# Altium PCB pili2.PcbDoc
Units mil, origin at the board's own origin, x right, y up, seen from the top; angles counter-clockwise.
Board outline 3240 x 2595 mil, 2 copper layers (Top Layer, Bottom Layer); 29 components, 28 nets, 78 pads, 0 vias.
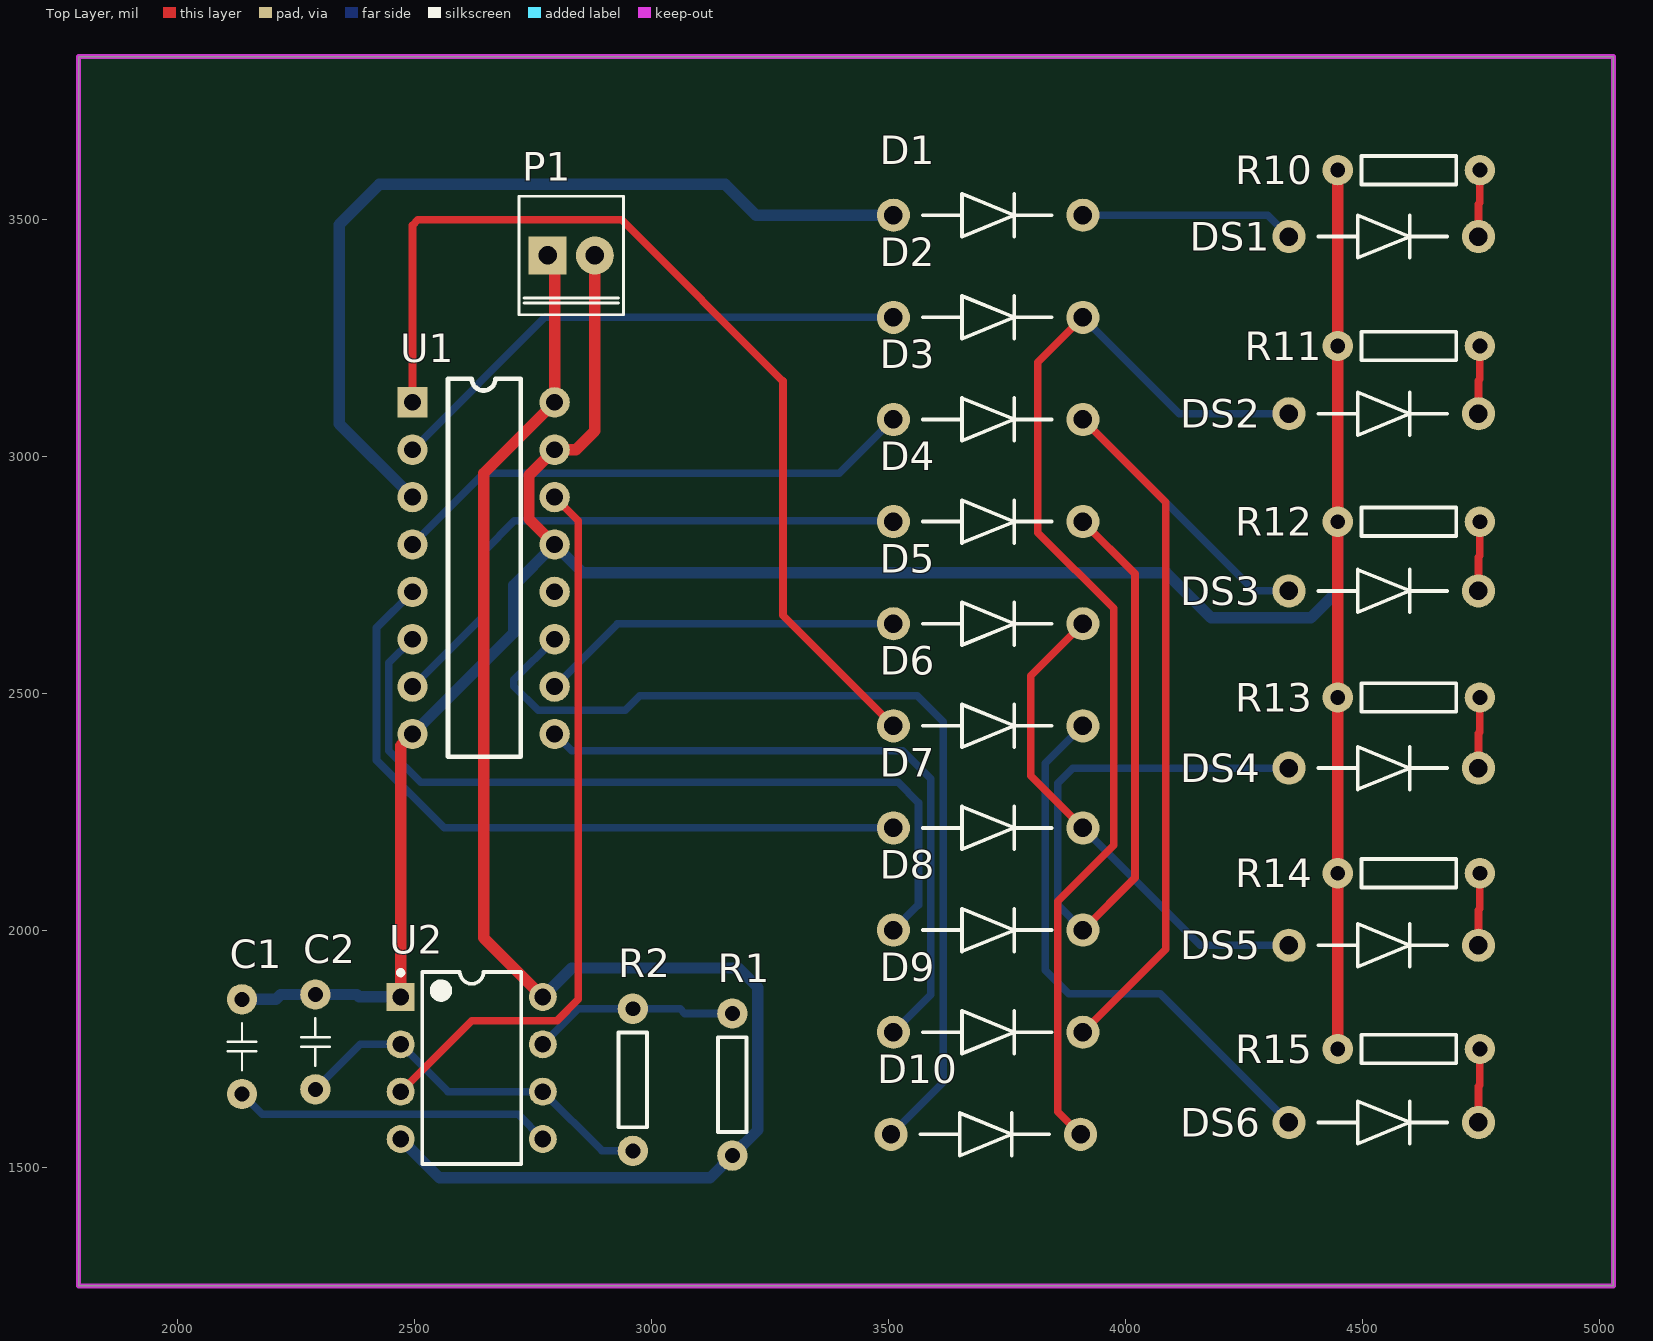
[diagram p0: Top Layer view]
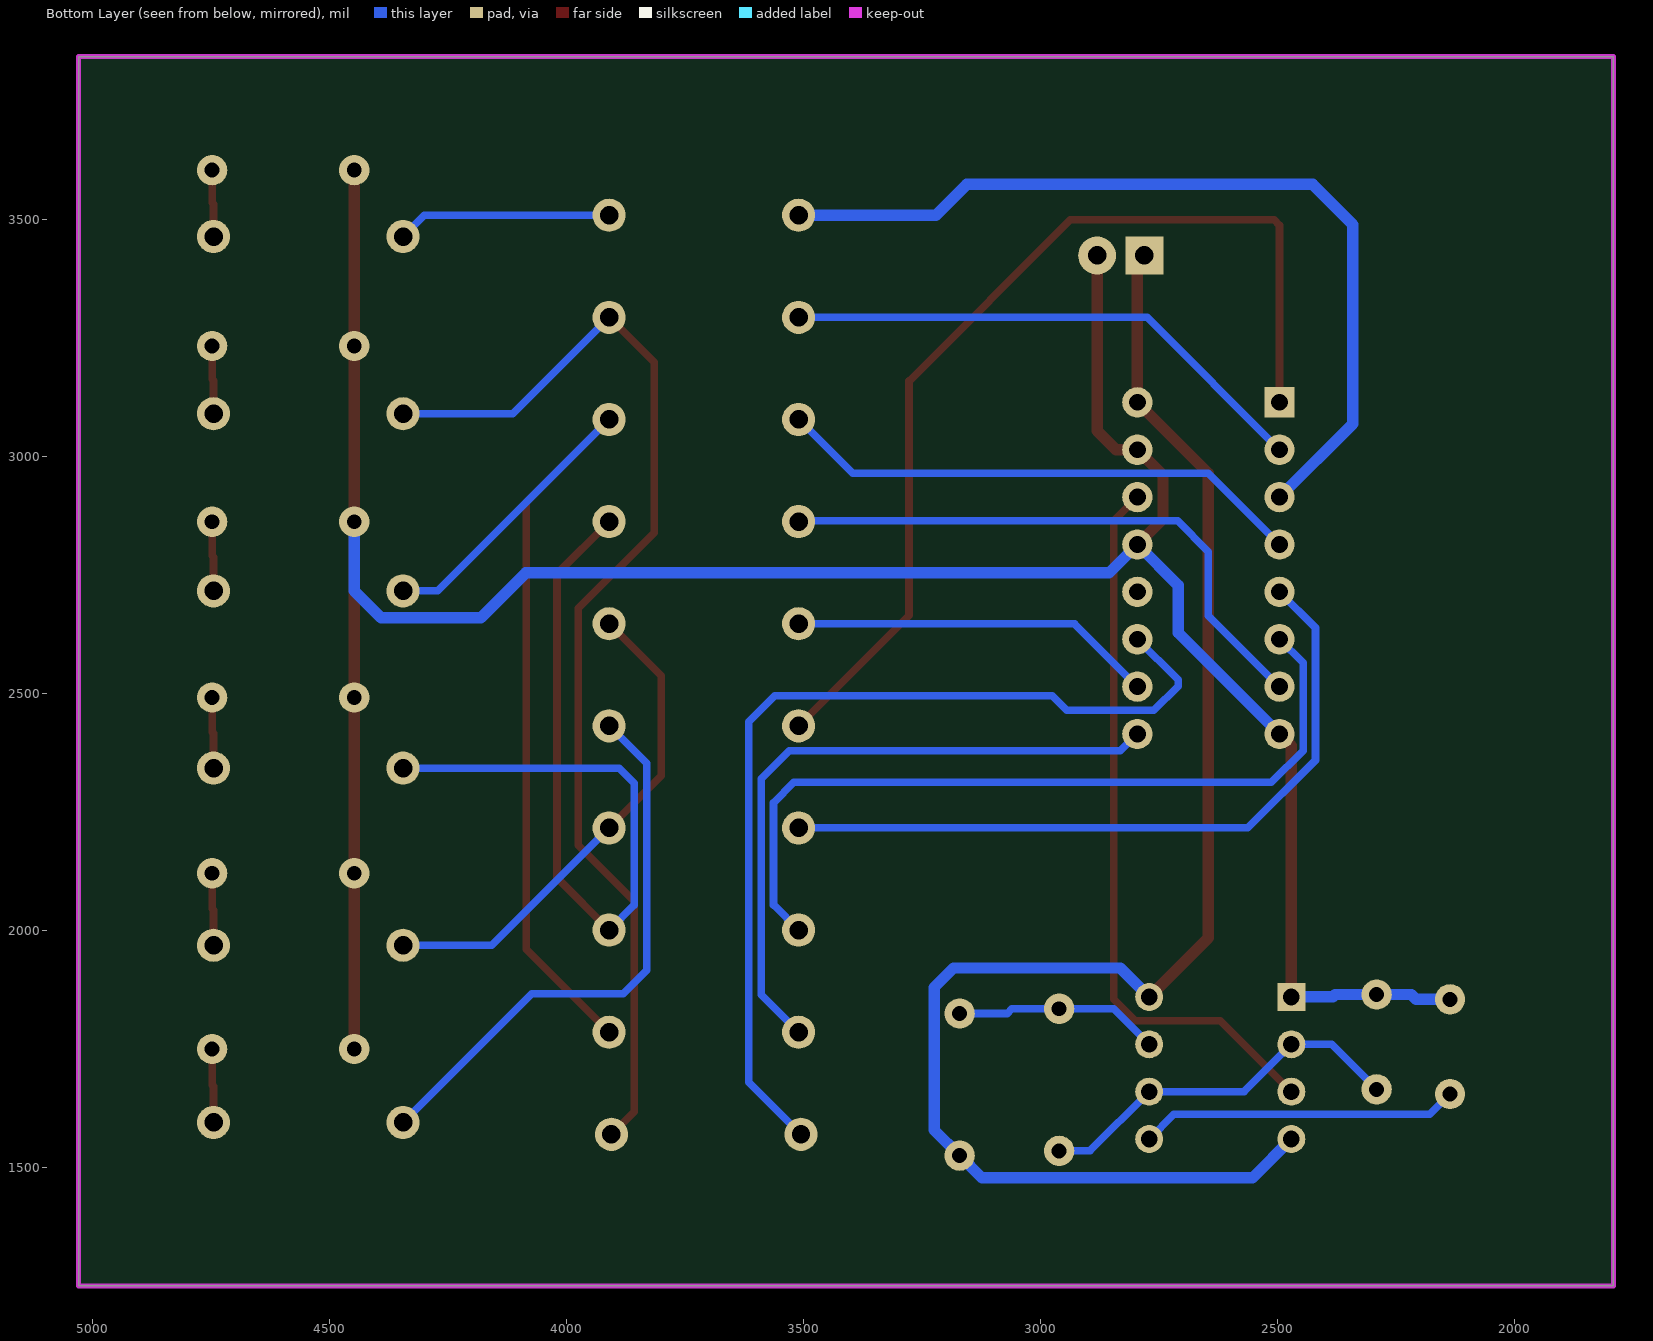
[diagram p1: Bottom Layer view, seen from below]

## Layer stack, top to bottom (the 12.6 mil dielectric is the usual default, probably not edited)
Top Layer: signal copper 1.4
Dielectric: dielectric 12.6, FR-4, Dk 4.8
Bottom Layer: signal copper 1.4

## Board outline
1790,1250 1790,3845 5030,3845 5030,1250

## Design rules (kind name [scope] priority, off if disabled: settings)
Clearance [All] p1: gap=10
PolygonConnect [All] p1: connectstyle=Relief reliefconductorwidth=10 reliefentries=4 polygonreliefangle="90 Angle" airgapwidth=10
RoutingVias [All] p1: holewidth=28 width=50 viastyle="Through Hole" minholewidth=28 minwidth=50 maxholewidth=28 maxwidth=50
SolderMaskExpansion [All] p1: expansion=4
Width Width_power [InNetClass('power')] p1: maxlimit=40 minlimit=10 preferedwidth=24
Width [All] p2: maxlimit=40 minlimit=10 preferedwidth=16
28 further rules are at their usual default settings.

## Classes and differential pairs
net class power: GND VCC

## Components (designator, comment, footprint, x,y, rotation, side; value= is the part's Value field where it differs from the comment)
C1 "Cap" "C200 - 1" 2135,1755 r180 top
C2 "Cap" "C200 - 1" 2290,1765 r180 top
D1 "1N914" D400 3710,3510 r0 top
D2 "1N914" D400 3710,3294.44 r0 top
D3 "1N914" D400 3710,3078.89 r0 top
D4 "1N914" D400 3710,2863.33 r0 top
D5 "1N914" D400 3710,2647.78 r0 top
D6 "1N914" D400 3710,2432.22 r0 top
D7 "1N914" D400 3710,2216.67 r0 top
D8 "1N914" D400 3710,2001.11 r0 top
D9 "1N914" D400 3710,1785.56 r0 top
D10 "1N914" D400 3705,1570 r0 top
DS1 "1N914" D400-1 4545,3465 r0 top
DS2 "1N914" D400-1 4545,3091 r0 top
DS3 "1N914" D400-1 4545,2717 r0 top
DS4 "1N914" D400-1 4545,2343 r0 top
DS5 "1N914" D400-1 4545,1969 r0 top
DS6 "1N914" D400-1 4545,1595 r0 top
P1 "+5V" "HEADER 2 PW-0.2" 2830,3425 r270 top
R1 "1k" AXIAL-0.3 3170,1675 r270 top
R2 "1k" AXIAL-0.3 2960,1685 r90 top
R10 "1k" AXIAL-0.3 4598,3605 r0 top
R11 "1k" AXIAL-0.3 4598,3234 r0 top
R12 "1k" AXIAL-0.3 4598,2863 r0 top
R13 "1k" AXIAL-0.3 4598,2492 r0 top
R14 "1k" AXIAL-0.3 4598,2121 r0 top
R15 "1k" AXIAL-0.3 4598,1750 r0 top
U1 "CD4017BCN" DIP16_4017 2495,3115 r270 top
U2 "LMC555CN" N08E_555 2620,1710 r0 top

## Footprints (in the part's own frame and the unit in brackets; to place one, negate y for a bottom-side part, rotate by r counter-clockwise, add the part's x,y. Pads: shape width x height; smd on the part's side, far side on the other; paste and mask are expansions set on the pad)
AXIAL-0.3 [mil] "0.3\" Resistor; 2 Leads"
  round 64 hole 31.5: 1(-150,0) 2(150,0)
  silkscreen extent -100,-30 100,30, body extent -161,-41 165,41, height 88
"C200 - 1" [mil] "吵病筿甧竟"
  round 64 hole 31.5: 1(0,100) 2(0,-100)
  silkscreen extent -30,-50 30,50, body extent -19,-132 21,143, height 282
D400 [mil]
  round 70 hole 39: 1(-200,0) 2(200,0)
  silkscreen extent -138,-45 134,45, body extent -216,-79 217,78, height 161
D400-1 [mil]
  round 70 hole 39: 1(-200,0) 2(200,0)
  silkscreen extent -138,-45 134,45, body extent -216,-59 217,59, height 141
DIP16_4017 [mil] "4017"
  rect 64x64 hole 35.43: 1(0,0)
  round 64 hole 35.43: 2(100,0) 3(200,0) 4(300,0) 5(400,0) 6(500,0) 7(600,0) 8(700,0) 9(700,300) 10(600,300) 11(500,300) 12(400,300) 13(300,300) 14(200,300) 15(100,300) 16(0,300)
  silkscreen extent -50,75 748,228, body extent -50,-4 748,304, height 177
"HEADER 2 PW-0.2" [mil]
  rect 80x80 hole 39: 1(0,-50)
  round 80 hole 39: 2(0,50)
  silkscreen extent -125,-110 125,110, body extent -124,-110 125,113, height 433
N08E_555 [mm]
  rect 1.5x1.5 hole 0.9: 1(-3.81,3.81)
  round 1.5 hole 0.9: 2(-3.81,1.27) 3(-3.81,-1.27) 4(-3.81,-3.81) 5(3.81,-3.81) 6(3.81,-1.27) 7(3.81,1.27) 8(3.81,3.81)
  silkscreen extent -3.93,-5.15 2.65,5.23, body extent -3.92,-5.15 3.92,5.15, height 4.5

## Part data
C1 C2: "Capacitor"
D1 D2 D3 D4 D5 D6 D7 D8 D9 D10 DS1 DS2 DS3 DS4 DS5 DS6: "High Conductance Fast Diode"
P1: library part "Header 2", "Header, 2-Pin"
R1 R2 R10 R11 R12 R13 R14 R15: library part Res, "Resistor"
U1: "Decade Counter/Divider with 10 Decoded Outputs"
U2: "CMOS Timer"

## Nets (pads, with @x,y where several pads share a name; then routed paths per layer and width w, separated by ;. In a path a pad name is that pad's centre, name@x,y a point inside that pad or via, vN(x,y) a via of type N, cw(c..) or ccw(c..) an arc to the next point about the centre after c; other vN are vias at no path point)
GND: C1.2 C2.2 P1.2 R10.1 R11.1 R12.1 R13.1 R14.1 R15.1 U1.8 U1.13 U1.15 U2.1 | length 5888.9
  Top Layer w24: U2.1 2470,2390 U1.8 ; U1.13 2741,2869 2741,2961 U1.15 2840,3015 2880,3055 P1.2 ; R15.1 R14.1 R13.1 R12.1 R11.1 R10.1
  Bottom Layer w24: C1.2 2207,1855 2217,1865 C2.2 2377,1865 2382,1860 U2.1 ; U1.8 2709,2629 2709,2729 U1.13 2855,2755 4086,2755 4181,2660 4391,2660 4448,2717 R12.1
NetC1_1: C1.1 U2.5 | length 674.4
  Bottom Layer w16: C1.1 2178,1612 2718,1612 U2.5
NetD1_1: D1.1 U1.3 | length 1871.3
  Bottom Layer w24: U1.3 2340,3070 2340,3490 2425,3575 3155,3575 3220,3510 D1.1
NetD2_1: D2.1 U1.2 | length 1130.7
  Bottom Layer w16: U1.2 2774.44,3294.44 D2.1
NetD3_1: D3.1 U1.4 | length 1124.3
  Bottom Layer w16: U1.4 2645,2965 3396.11,2965 D3.1
NetD4_1: D4.1 U1.7 | length 1240.7
  Bottom Layer w16: U1.7 2645,2665 2645,2800 2710,2865 3485,2865 3485,2863.33 D4.1
NetD5_1: D5.1 U1.10 | length 770
  Bottom Layer w16: U1.10 2927.78,2647.78 D5.1
NetD6_1: D6.1 U1.1 | length 2125.7
  Top Layer w16: U1.1 2495,3489 2506,3500 2937,3500 3277,3160 3277,2665.22 D6.1
NetD7_1: D7.1 U1.5 | length 1536.9
  Bottom Layer w16: U1.5 2419,2639 2419,2360 2562.33,2216.67 D7.1
NetD8_1: D8.1 U1.6 | length 1710.1
  Bottom Layer w16: U1.6 2445,2565 2445,2380 2512.23,2312.77 3520.23,2312.77 3563,2270 3563,2054.11 D8.1
NetD9_1: D9.1 U1.9 | length 1400.5
  Bottom Layer w16: U1.9 2830.78,2379.22 3529.78,2379.22 3589,2320 3589,1864.56 D9.1
NetD10_1: D10.1 U1.11 | length 2013.9
  Bottom Layer w16: U1.11 2709,2529 2709,2516 2760,2465 2944,2465 2975,2496 3560,2496 3615,2441 3615,1680 D10.1
NetDS1_2: DS1.2 R10.2 | length 141.2
  Top Layer w16: DS1.2 4745,3533 4748,3536 R10.2
NetDS2_2: DS2.2 R11.2 | length 144.2
  Top Layer w16: DS2.2 4745,3161 4748,3164 R11.2
NetDS3_2: DS3.2 R12.2 | length 147.2
  Top Layer w16: DS3.2 4745,2788 4748,2791 R12.2
NetDS4_2: DS4.2 R13.2 | length 150.2
  Top Layer w16: DS4.2 4745,2416 4748,2419 R13.2
NetDS5_2: DS5.2 R14.2 | length 153.2
  Top Layer w16: DS5.2 4745,2043 4748,2046 R14.2
NetDS6_2: DS6.2 R15.2 | length 156.2
  Top Layer w16: DS6.2 4745,1671 4748,1674 R15.2
NetR1_1: R1.1 R2.2 U2.7 | length 435.2
  Bottom Layer w16: U2.7 2845,1835 R2.2 3060,1835 3070,1825 R1.1
O1: D1.2 DS1.1 | length 453.6
  Bottom Layer w16: D1.2 4300,3510 DS1.1
O2: D2.2 D10.2 DS2.1 | length 2418.1
  Top Layer w16: D10.2 3857,1618 3857,2062 3975,2180 3975,2680 3815,2840 3815,3199.44 D2.2
  Bottom Layer w16: D2.2 4113.44,3091 DS2.1
O3: D3.2 D9.2 DS3.1 | length 2023.2
  Top Layer w16: D9.2 4085,1960.56 4085,2903.89 D3.2
  Bottom Layer w16: D3.2 4271.89,2717 DS3.1
O4: D4.2 D8.2 DS4.1 | length 1786.4
  Top Layer w16: D8.2 4020,2111.11 4020,2753.33 D4.2
  Bottom Layer w16: D8.2 3857,2054.11 3857,2311 3889,2343 DS4.1
O5: D5.2 D7.2 DS5.1 | length 1059.8
  Top Layer w16: D7.2 3800,2326.67 3800,2537.78 D5.2
  Bottom Layer w16: D7.2 4157.67,1969 DS5.1
O6: D6.2 DS6.1 | length 1195.9
  Bottom Layer w16: D6.2 3831,2353.22 3831,1916 3880,1867 4073,1867 DS6.1
OUT: U1.14 U2.3 | length 1536.5
  Top Layer w16: U2.3 2620,1810 2800,1810 2845,1855 2845,2865 U1.14
TR: C2.1 R2.1 U2.2 U2.6 | length 802.5
  Bottom Layer w16: C2.1 2385,1760 U2.2 2570,1660 U2.6 2895,1535 R2.1
VCC: P1.1 R1.2 U1.16 U2.4 U2.8 | length 3312.2
  Top Layer w24: U2.8 2645,1985 2645,2965 U1.16 2795,3410 P1.1
  Bottom Layer w24: U2.4 2552,1478 3123,1478 R1.2 3224,1579 3224,1880 3183,1921 2831,1921 U2.8
pads on no net: U1.12

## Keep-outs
Keep-Out Layer:
  the board outline again, w10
